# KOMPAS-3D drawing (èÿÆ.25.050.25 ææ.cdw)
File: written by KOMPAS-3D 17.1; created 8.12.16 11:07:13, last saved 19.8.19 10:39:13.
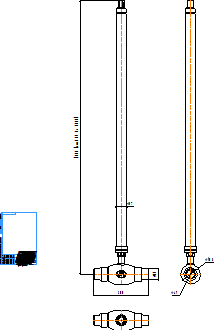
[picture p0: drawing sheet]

Sheet 1: A4, portrait

Title block, sheet 1: name: КШТ.25.050.25 С/С; sheets: 1; organisation: ООО "Торговый дом АДЛ"; sheet format: A4; stored path: C:\Users\kka\KOMPAS_Work\Модели кранов для исследований\DN65\С удлинением\КШГ.35.050.25 СС ГЧ _ Шаровой кран БИВАЛ Ду50 Ру2,5 МПа полнопроходной под приварку, c удлинением штока H=950 Габаритный чертеж Lстр600.cdw

Views: Вид 1, Проекционный вид 2, Проекционный вид 3
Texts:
  Klimkovich
  ADL
  (от 287 до 5000)
  Рама для чертежей
  Лит-Масса-Масштаб
  Материал-Предприятие
  Масштаб
  Изм.
  Лист
  № докум.
  Подп.
  Дата
  Лит.
  Разраб.
  Пров.
  Т.контр.
  Листов
  Внимание! Данный продукт является объектом авторского права ООО «Торговый Дом АДЛ».
  Запрещается изменение, копирование, распространение
  (в том числе путем копирования на другие сайты и ресурсы в Интернете)
  или любое иное использование информации и объектов без предварительного
  согласия правообладателя (ООО «Торговый Дом АДЛ»).
  Н.контр.
  Утв.
  Изменение
  Номер документа
  Подпись
  Обозначение документа
  Наименование изделия
  Масса изделия по ГОСТ 2.109-73
  Порядковый номер листа
  Общее количество листов в документе
  Характер работы, выполненной лицом, подписавшим документ
  Наименование или индекс предприятия, выпускающего документ
  Инв. № подл.
  Подп. и дата
  Взам. инв. №
  Инв. № дубл.
  Инвентарный номер подлинника по ГОСТ 2.501-68
  Подпись принявшего подлинник в отдел технической документации
  Инвентарный номер подлинника, взамен которого выпущен данный подлинник
  Инвентарный номер дубликата по ГОСТ 2.502-68
  Подпись принявшего дубликат в отдел технической документации
  Справ. №
  Перв. примен.
  Обозначение документа, взамен или на основании которого выпущен данный документ
  Обозначение документа, в котором впервые записан данный документ
  Подпись лица, копировавшего чертеж
  Обозначение формата листа
  !Рама для чертежа
Dimensions and other numbers on the sheet: 57; 1500; 300; 49; 108; 1:1; 1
